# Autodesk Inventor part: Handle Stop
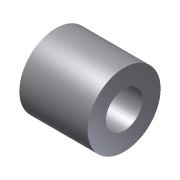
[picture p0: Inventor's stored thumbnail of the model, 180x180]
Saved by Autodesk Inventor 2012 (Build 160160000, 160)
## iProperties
Shininess: 77.0
Length Units: 11269
Angle Units: 11279
Time Units: 11290
Mass Units: 11283
Length Display Precision: 3
Angle Display Precision: 2
Compacted: True
Created: 2002-02
Part Number: Handle Stop
Document SubType Name: Modeling
Designer: ***
Density: 1 g/cm^3
Material: Default
Mass: 2.36248 g
Surface Area: 14.8283 cm^2
Volume: 2.36248 cm^3
Density: 0.0
Volumn: 0.0
Area: 0.0
PropertySet Name: Model Information
Control State: 0
Master: False
Checked Out: False
Author: ***
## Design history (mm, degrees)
sketch "Sketch1"
  geometry: L1 (0, 0)-(0, -2); L2 (0, -2)-(8, -2); L3 (8, -2)-(8, 13); L4 (8, 13)-(4, 13); L5 (4, 13)-(4, 0); L6 (4, 0)-(0, 0)
  constraints: 12 end point, 4 parallel, 1 perpendicular, 1 vertical
  dimensions: "d0" = 16 diameter of L3 L1; "d1" = 8 diameter of L5 L1; "d2" = 2 distance of L1.start L1.end; "d3" = 15 distance of L2.end L3.end
revolve "Revolution1" sketch "Sketch1" stored, may be unused: angle "d4" = 90 deg
body "Solid1"
